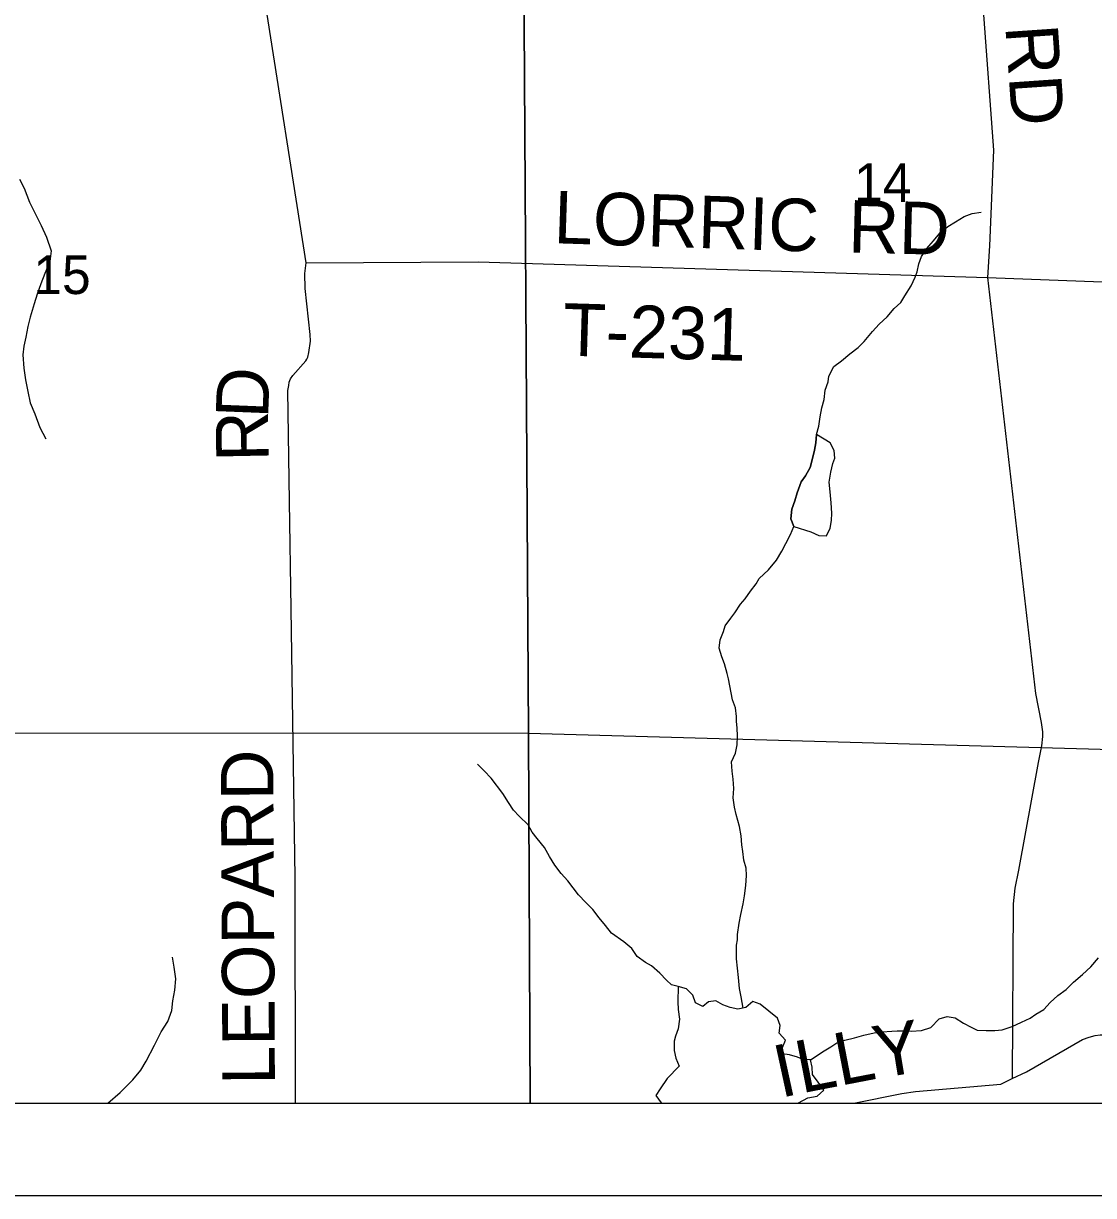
# Model space of a CAD drawing. Extents: x 0 to 34, y 0 to 22.
# Drawn here: x 3.716 to 4.875, y 14 to 15.27 of the extents above; entities that cross this region are included whole.
import ezdxf

# ---------------------------------------------------------------- set-up
doc = ezdxf.new("R2010")
doc.units = 0
for name, color, linetype in [('Default', 7, 'Continuous'), ('SH_Cut_Line', 7, 'Continuous'), ('SH_Data', 7, 'Continuous')]:
    doc.layers.add(name, color=color, linetype=linetype)

msp = doc.modelspace()

# ---------------------------------------------------------------- linework, layer by layer
at = {"layer": 'Default'}
for p, q in [((4.0219, 15.0104), (3.9291, 15.6027)), ((4.7599, 14.9946), (4.977, 14.9865))]:
    msp.add_line(p, q, dxfattribs=at)
for points in [[(2.1, 17.0156), (2.1, 14.1), (6.2892, 14.1), (6.2892, 14.18), (6.2889, 14.4906), (6.2926, 14.8972), (6.2959, 15.2705), (6.2922, 16.0152), (6.2871, 17.0188)], [(4.7553, 15.2841), (4.7664, 15.1324), (4.7622, 15.0289), (4.7599, 14.9946)], [(3.7115, 15.1011), (3.7166, 15.0913), (3.7222, 15.0762), (3.7296, 15.0616), (3.7351, 15.051), (3.7409, 15.0382), (3.7457, 15.0235), (3.7444, 15.0118), (3.739, 14.9988), (3.7346, 14.9877), (3.7307, 14.9763), (3.7274, 14.966), (3.7232, 14.9515), (3.7207, 14.9416), (3.7182, 14.9298), (3.7161, 14.9203), (3.7152, 14.9108), (3.7162, 14.8964), (3.7179, 14.8835), (3.7204, 14.871), (3.7232, 14.8586), (3.7283, 14.8469), (3.7335, 14.8322), (3.7401, 14.8198)], [(4.4952, 14.203), (4.4933, 14.2153), (4.4913, 14.2244), (4.4904, 14.2361), (4.4894, 14.2464), (4.4882, 14.2566), (4.4881, 14.2623), (4.4883, 14.2714), (4.4894, 14.2771), (4.4893, 14.2828), (4.491, 14.295), (4.4928, 14.3045), (4.4953, 14.316), (4.4967, 14.3247), (4.4984, 14.3358), (4.499, 14.3468), (4.4985, 14.3548), (4.4961, 14.3635), (4.4949, 14.3726), (4.494, 14.3798), (4.4931, 14.3896), (4.4914, 14.3999), (4.4878, 14.4127), (4.4858, 14.4207), (4.4845, 14.4309), (4.4851, 14.4408), (4.4846, 14.4511), (4.4833, 14.4598), (4.4828, 14.47), (4.4872, 14.4792), (4.489, 14.4884), (4.4893, 14.4975), (4.4887, 14.5066), (4.4883, 14.5134), (4.4882, 14.5191), (4.4869, 14.5282), (4.4838, 14.5369), (4.4796, 14.5597), (4.478, 14.5657), (4.4752, 14.5759), (4.4721, 14.5835), (4.4693, 14.5929), (4.4703, 14.6021), (4.4739, 14.6112), (4.4758, 14.6173), (4.4821, 14.6254), (4.4862, 14.6312), (4.4925, 14.6408), (4.4977, 14.6465), (4.5033, 14.6546), (4.5093, 14.6626), (4.5126, 14.6684), (4.5227, 14.678), (4.5313, 14.6884), (4.5373, 14.698), (4.5417, 14.7064), (4.5465, 14.716), (4.5502, 14.7248), (4.547, 14.7331), (4.548, 14.7434), (4.5513, 14.7525), (4.5538, 14.7613), (4.5582, 14.7731), (4.563, 14.7797), (4.5679, 14.7888), (4.5704, 14.7984), (4.5725, 14.8075), (4.5739, 14.8155), (4.5749, 14.8243), (4.5775, 14.8334), (4.5788, 14.8437), (4.5806, 14.8532), (4.5831, 14.8624), (4.5841, 14.8726), (4.5874, 14.8814), (4.5881, 14.8875), (4.5936, 14.8982), (4.6019, 14.9044), (4.6109, 14.9118), (4.6199, 14.9187), (4.6263, 14.9253), (4.6356, 14.936), (4.6427, 14.9441), (4.6513, 14.9518), (4.6588, 14.9611), (4.6663, 14.9676), (4.6704, 14.9745), (4.6774, 14.9856), (4.6815, 14.9948), (4.6837, 15.0005), (4.6858, 15.0093), (4.6887, 15.0173), (4.6939, 15.0257), (4.7014, 15.0342), (4.7085, 15.0427), (4.7171, 15.0496), (4.7254, 15.0547), (4.7348, 15.0605), (4.7435, 15.0637), (4.753, 15.0653)], [(4.0041, 14.7519), (4.0023, 14.8722), (4.0031, 14.8777), (4.0037, 14.8813), (4.0052, 14.8848), (4.0077, 14.8882), (4.0218, 14.9041), (4.0228, 14.9061), (4.0238, 14.9084), (4.025, 14.9132), (4.0266, 14.9256), (4.0265, 14.9327), (4.021, 14.9827), (4.0207, 14.999), (4.0219, 15.0104)], [(4.0219, 15.0104), (4.2085, 15.0114), (4.7599, 14.9946)], [(4.7599, 14.9946), (4.8121, 14.5437), (4.8181, 14.5123), (4.8197, 14.5023), (4.8197, 14.4974), (4.8184, 14.4871), (4.8148, 14.4692), (4.7936, 14.3525), (4.7896, 14.333), (4.7879, 14.3159), (4.7867, 14.1267)], [(4.5749, 14.8243), (4.5739, 14.8155), (4.5725, 14.8075), (4.5704, 14.7984), (4.5679, 14.7888), (4.563, 14.7797), (4.5582, 14.7731), (4.5538, 14.7613), (4.5513, 14.7525), (4.548, 14.7434), (4.547, 14.7331), (4.5502, 14.7248)], [(4.5502, 14.7248), (4.5685, 14.719), (4.5773, 14.7149), (4.5856, 14.7146), (4.5897, 14.7231), (4.5911, 14.7314), (4.5913, 14.7394), (4.5908, 14.7504), (4.5895, 14.7622), (4.5886, 14.7728), (4.5903, 14.7835), (4.5925, 14.793), (4.5947, 14.7987), (4.5938, 14.8071), (4.5895, 14.8154), (4.5749, 14.8243)], [(4.0105, 14.1), (4.0101, 14.3445), (4.0059, 14.6355), (4.0041, 14.7519)], [(4.3529, 14.2843), (4.3463, 14.2925), (4.3394, 14.3008), (4.3324, 14.3098), (4.3251, 14.3173), (4.317, 14.3259), (4.3054, 14.341), (4.2984, 14.3488), (4.2915, 14.3579), (4.2856, 14.3673), (4.2802, 14.3771), (4.2721, 14.3868), (4.267, 14.3936), (4.2624, 14.4015), (4.2527, 14.4109), (4.2466, 14.4176), (4.2411, 14.4259), (4.2349, 14.4357), (4.2225, 14.4522), (4.2148, 14.4601), (4.2075, 14.4672)], [(4.5546, 14.1), (4.5553, 14.1006), (4.5655, 14.1057), (4.5754, 14.1078), (4.5829, 14.114), (4.5767, 14.123), (4.5705, 14.1313), (4.57, 14.1392), (4.5683, 14.1472), (4.56, 14.1474), (4.5543, 14.15), (4.5455, 14.1526), (4.5375, 14.1536), (4.5378, 14.1604), (4.5411, 14.1685), (4.5345, 14.176), (4.5355, 14.1843), (4.5324, 14.1923), (4.5232, 14.1997), (4.5136, 14.2072), (4.5059, 14.2101), (4.4984, 14.2036), (4.4897, 14.2019), (4.4813, 14.2037), (4.4733, 14.2066), (4.4657, 14.2111), (4.4577, 14.2098), (4.4517, 14.2048), (4.4437, 14.2089), (4.4409, 14.2172), (4.4339, 14.2239), (4.4248, 14.2264), (4.4179, 14.2282), (4.4122, 14.2335), (4.4052, 14.241), (4.396, 14.2488), (4.3895, 14.2525), (4.3807, 14.2589), (4.3748, 14.2675), (4.366, 14.275), (4.3529, 14.2843)], [(3.8068, 14.1), (3.8072, 14.1002), (3.8206, 14.1118), (3.8343, 14.1253), (3.8428, 14.1357), (3.8487, 14.1457), (3.8579, 14.1629), (3.8648, 14.1774), (3.8722, 14.1886), (3.8765, 14.2004), (3.8775, 14.211), (3.8799, 14.2224), (3.8808, 14.2346), (3.8791, 14.2475), (3.8774, 14.2581)], [(4.5683, 14.1472), (4.583, 14.1569), (4.5905, 14.1612), (4.5969, 14.1654), (4.6056, 14.1682), (4.6159, 14.1707), (4.6261, 14.1738), (4.6374, 14.1763), (4.6458, 14.1775), (4.6564, 14.1781), (4.6621, 14.1785), (4.6689, 14.1783), (4.6773, 14.178), (4.6887, 14.1789), (4.6985, 14.1821), (4.7078, 14.1913), (4.7162, 14.1941), (4.7249, 14.1927), (4.7341, 14.1868), (4.7425, 14.1823), (4.749, 14.179), (4.7585, 14.1788), (4.768, 14.1789), (4.776, 14.1794), (4.7869, 14.183), (4.7968, 14.1877), (4.8062, 14.192), (4.8122, 14.1966), (4.8209, 14.2017), (4.828, 14.209), (4.8362, 14.2167), (4.8452, 14.2233), (4.8531, 14.231), (4.8628, 14.2395), (4.8718, 14.2476), (4.8801, 14.2576)], [(4.4248, 14.2264), (4.4247, 14.2097), (4.4248, 14.2014), (4.4264, 14.1911), (4.4251, 14.1805), (4.4221, 14.1728), (4.4207, 14.1671), (4.4205, 14.1572), (4.4225, 14.1489), (4.426, 14.1402), (4.4129, 14.1267), (4.4055, 14.1156), (4.4007, 14.1083), (4.4065, 14.1004), (4.4066, 14.1)], [(4.5546, 14.1), (4.5553, 14.1006), (4.5655, 14.1057), (4.5754, 14.1078), (4.5829, 14.114), (4.5767, 14.123), (4.5705, 14.1313), (4.57, 14.1392), (4.5683, 14.1472), (4.56, 14.1474), (4.5543, 14.15), (4.5455, 14.1526), (4.5375, 14.1536), (4.5378, 14.1604), (4.5411, 14.1685), (4.5345, 14.176), (4.5355, 14.1843), (4.5324, 14.1923), (4.5232, 14.1997), (4.5136, 14.2072), (4.5059, 14.2101), (4.4984, 14.2036), (4.4897, 14.2019), (4.4813, 14.2037), (4.4733, 14.2066), (4.4657, 14.2111), (4.4577, 14.2098), (4.4517, 14.2048), (4.4437, 14.2089), (4.4409, 14.2172), (4.4339, 14.2239), (4.4248, 14.2264)], [(4.6153, 14.1), (4.6671, 14.1106), (4.6819, 14.1126), (4.7744, 14.1208), (4.7867, 14.1267), (4.8024, 14.1341), (4.8629, 14.1689), (4.8701, 14.1715), (4.8766, 14.1733), (4.882, 14.174), (4.8863, 14.1742), (4.8968, 14.1742), (4.9356, 14.1735), (4.9981, 14.173)]]:
    msp.add_lwpolyline(points, dxfattribs=at)
for points in [[(4.2566, 15.5062), (4.2629, 14.5006), (3.2648, 14.5009), (3.2514, 15.5272)], [(4.2566, 15.5062), (5.284, 15.4777), (5.2822, 14.472), (4.2629, 14.5006)], [(3.2645, 14.1), (4.2648, 14.1), (4.2629, 14.5006), (3.2648, 14.5009)], [(4.2648, 14.1), (5.2827, 14.1), (5.2822, 14.472), (4.2629, 14.5006)]]:
    msp.add_lwpolyline(points, close=True, dxfattribs=at)
at = {"layer": 'SH_Cut_Line'}
msp.add_lwpolyline([(2.1, 17.0156), (2.1, 14.1), (8.9, 14.1), (8.9, 17.02)], dxfattribs=at)
at = {"layer": 'SH_Data'}
for p, q in [((2.1, 14.1), (8.9, 14.1)), ((2, 14), (9, 14))]:
    msp.add_line(p, q, dxfattribs=at)

# ---------------------------------------------------------------- texts
at = {"layer": 'Default'}
for s, height, rotation, p in [('RD', 0.05682, 273.9449, (4.7793, 15.2667)), ('14', 0.04186, 0, (4.6156, 15.0764)), ('LORRIC', 0.05682, 358.1286, (4.2896, 15.0317)), ('RD', 0.05682, 358.5175, (4.6087, 15.0217)), ('15', 0.04186, 0, (3.7264, 14.9766)), ('T-231', 0.05682, 358.3152, (4.2994, 14.91)), ('D', 0.0568, 87.7081, (3.9807, 14.8413)), ('R', 0.0568, 91.1281, (3.9816, 14.7955)), ('LEOPARD', 0.05682, 90.2974, (3.9882, 14.1201)), ('Y', 0.0568, 9.3671, (4.6413, 14.1267)), ('L', 0.0568, 10.9124, (4.6, 14.1188)), ('I', 0.0568, 12.2621, (4.5358, 14.1057)), ('L', 0.0568, 11.0351, (4.5583, 14.1106))]:
    msp.add_text(s, height=height, rotation=rotation, dxfattribs=at).set_placement(p)

doc.saveas('drawing.dxf')
